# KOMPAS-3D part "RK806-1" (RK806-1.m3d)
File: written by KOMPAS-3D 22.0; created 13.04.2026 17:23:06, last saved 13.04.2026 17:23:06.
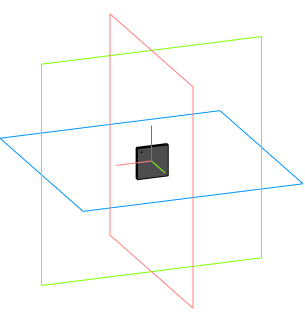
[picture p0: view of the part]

Document properties: Автор: Andrey; Полное имя файла: C:\Users\User1\Documents\RK806-1.m3d

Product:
- Part/product: RK806-1

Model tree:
1. Операция без истории:1
2. Операция без истории:2
3. Операция без истории:3
4. Операция без истории:4
5. Операция без истории:5
6. Операция без истории:6
7. Операция без истории:7
8. Операция без истории:8
9. Операция без истории:9
10. Операция без истории:10
11. Операция без истории:11
12. Операция без истории:12
13. Операция без истории:13
14. Операция без истории:14
15. Операция без истории:15
16. Операция без истории:16
17. Операция без истории:17
18. Операция без истории:18
19. Операция без истории:19
20. Операция без истории:20
21. Операция без истории:21
22. Операция без истории:22
23. Операция без истории:23
24. Операция без истории:24
25. Операция без истории:25
26. Операция без истории:26
27. Операция без истории:27
28. Операция без истории:28
29. Операция без истории:29
30. Операция без истории:30
31. Операция без истории:31
32. Операция без истории:32
33. Операция без истории:33
34. Операция без истории:34
35. Операция без истории:35
36. Операция без истории:36
37. Операция без истории:37
38. Операция без истории:38
39. Операция без истории:39
40. Операция без истории:40
41. Операция без истории:41
42. Операция без истории:42
43. Операция без истории:43
44. Операция без истории:44
45. Операция без истории:45
46. Операция без истории:46
47. Операция без истории:47
48. Операция без истории:48
49. Операция без истории:49
50. Операция без истории:50
51. Операция без истории:51
52. Операция без истории:52
53. Операция без истории:53
54. Операция без истории:54
55. Операция без истории:55
56. Операция без истории:56
57. Операция без истории:57
58. Операция без истории:58
59. Операция без истории:59
60. Операция без истории:60
61. Операция без истории:61
62. Операция без истории:62
63. Операция без истории:63
64. Операция без истории:64
65. Операция без истории:65
66. Операция без истории:66
67. Операция без истории:67
68. Операция без истории:68
69. Операция без истории:69
70. Операция без истории:70
71. Операция без истории:71

Expressions: RK806-1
